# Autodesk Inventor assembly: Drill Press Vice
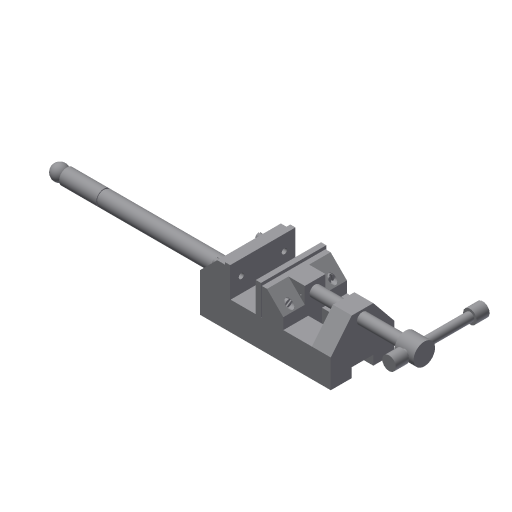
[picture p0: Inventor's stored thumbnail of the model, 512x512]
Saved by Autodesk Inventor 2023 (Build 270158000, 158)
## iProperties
Created: 2009-05
Part Number: Drill Press Vice
Document SubType Name: Assembly
Designer: Sham
Author: Sham
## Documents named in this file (9)
- D:\PROJECTS\Project 2022\Autodesk Inventor For Professional 2023\RESOURCES INVENTOR 2023\RESOURCES INVENTOR 2023\Inventor_2023_tut\Inventor_2023_tut\c12_Inv_2023_tut\c12_Inv_tut_2023\c12_tut03_inv\Drill Press Vice.iam
- D:\PROJECTS\Project 2022\Autodesk Inventor For Professional 2023\RESOURCES INVENTOR 2023\RESOURCES INVENTOR 2023\Inventor_2023_tut\Inventor_2023_tut\c12_Inv_2023_tut\c12_Inv_tut_2023\c12_tut03_inv\Base.ipt
- D:\PROJECTS\Project 2022\Autodesk Inventor For Professional 2023\RESOURCES INVENTOR 2023\RESOURCES INVENTOR 2023\Inventor_2023_tut\Inventor_2023_tut\c12_Inv_2023_tut\c12_Inv_tut_2023\c12_tut03_inv\Safety Handle.ipt
- D:\PROJECTS\Project 2022\Autodesk Inventor For Professional 2023\RESOURCES INVENTOR 2023\RESOURCES INVENTOR 2023\Inventor_2023_tut\Inventor_2023_tut\c12_Inv_2023_tut\c12_Inv_tut_2023\c12_tut03_inv\Jaw Face.ipt
- D:\PROJECTS\Project 2022\Autodesk Inventor For Professional 2023\RESOURCES INVENTOR 2023\RESOURCES INVENTOR 2023\Inventor_2023_tut\Inventor_2023_tut\c12_Inv_2023_tut\c12_Inv_tut_2023\c12_tut03_inv\Movable Jaw.ipt
- D:\PROJECTS\Project 2022\Autodesk Inventor For Professional 2023\RESOURCES INVENTOR 2023\RESOURCES INVENTOR 2023\Inventor_2023_tut\Inventor_2023_tut\c12_Inv_2023_tut\c12_Inv_tut_2023\c12_tut03_inv\Cap Screw.ipt
- D:\PROJECTS\Project 2022\Autodesk Inventor For Professional 2023\RESOURCES INVENTOR 2023\RESOURCES INVENTOR 2023\Inventor_2023_tut\Inventor_2023_tut\c12_Inv_2023_tut\c12_Inv_tut_2023\c12_tut03_inv\Clamp Screw Handle.ipt
- D:\PROJECTS\Project 2022\Autodesk Inventor For Professional 2023\RESOURCES INVENTOR 2023\RESOURCES INVENTOR 2023\Inventor_2023_tut\Inventor_2023_tut\c12_Inv_2023_tut\c12_Inv_tut_2023\c12_tut03_inv\Clamp Screw.ipt
- D:\PROJECTS\Project 2022\Autodesk Inventor For Professional 2023\RESOURCES INVENTOR 2023\RESOURCES INVENTOR 2023\Inventor_2023_tut\Inventor_2023_tut\c12_Inv_2023_tut\c12_Inv_tut_2023\c12_tut03_inv\Handle Stop.ipt
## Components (13 placed, 8 different names)
1. Base:1 — Mate:2, Mate:3, Mate:7, Insert:10, Insert:11, Insert:12, Insert:13
2. Safety Handle:1
3. Jaw Face:1 — Insert:8, Insert:9, Mate:7
4. Jaw Face:2 — Insert:10, Insert:11
5. Movable Jaw:1 — Mate:2, Mate:3, Insert:2, Insert:3, Insert:4, Insert:8, Insert:9
6. Cap Screw:1 — Insert:2
7. Cap Screw:2 — Insert:3
8. Cap Screw:3 — Insert:13
9. Cap Screw:4 — Insert:12
10. Clamp Screw:1 — Insert:4, Mate:6, Rotation/Translation:2
11. Clamp Screw Handle:1 — Mate:6, Insert:5, Insert:6, Rotation/Translation:2
12. Handle Stop:1 — Insert:6, Mate:8
13. Handle Stop:2 — Insert:5
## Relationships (17: Insert 11, Mate 5, RelateRotateTranslate 1)
- Mate:2: Base:1 ↔ Movable Jaw:1
- Mate:3: Base:1 ↔ Movable Jaw:1
- Insert:2: Movable Jaw:1 ↔ Cap Screw:1
- Insert:3: Movable Jaw:1 ↔ Cap Screw:2
- Insert:4: Movable Jaw:1 ↔ Clamp Screw:1
- Mate:6: Clamp Screw:1 ↔ Clamp Screw Handle:1
- Insert:5: Clamp Screw Handle:1 ↔ Handle Stop:2
- Insert:6: Clamp Screw Handle:1 ↔ Handle Stop:1
- Insert:8: Jaw Face:1 ↔ Movable Jaw:1
- Insert:9: Jaw Face:1 ↔ Movable Jaw:1
- Mate:7: Base:1 ↔ Jaw Face:1
- Rotation/Translation:2 [RelateRotateTranslate]: Clamp Screw:1 ↔ Clamp Screw Handle:1
- Mate:8: Handle Stop:1
- Insert:10: Base:1 ↔ Jaw Face:2
- Insert:11: Base:1 ↔ Jaw Face:2
- Insert:12: Base:1 ↔ Cap Screw:4
- Insert:13: Base:1 ↔ Cap Screw:3
